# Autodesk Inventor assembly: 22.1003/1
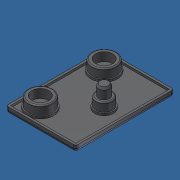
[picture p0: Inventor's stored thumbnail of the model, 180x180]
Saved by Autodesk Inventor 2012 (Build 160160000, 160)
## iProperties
Created: 2012-03
Part Number: 22.1003/1
Document SubType Name: Assembly
Designer: Administrator
Description: END CAP 45x32 Z GRAY
Vendor: S
Mass: 4.10321 g
Surface Area: 46.1556 cm^2
Volume: 3.87095 cm^3
Density: 1.06 g/cm^3
Author: Administrator
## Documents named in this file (3)
- C:\Andys Backup Data\ANDY'S INVENTOR\INVENTOR LIBRARIES\PARTS LIBRARY\END CAPS\22.1003_1 END CAP 45x32 Z Gray.iam
- C:\Andys Backup Data\ANDY'S INVENTOR\INVENTOR LIBRARIES\PARTS LIBRARY\END CAPS\SUBCOMPONENTS\22.1003_1 END CAP 45X32 GRAY.ipt
- C:\Andys Backup Data\ANDY'S INVENTOR\INVENTOR LIBRARIES\PARTS LIBRARY\END CAPS\SUBCOMPONENTS\END CAP DOWEL GRAY.ipt
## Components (2 placed, 2 different names)
1. 22.1003_1 END CAP 45X32 GRAY:1 — Mate:1, Flush:1
2. END CAP DOWEL GRAY:1 — Mate:1, Flush:1
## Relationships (2: Mate 1, Flush 1)
- Mate:1: 22.1003_1 END CAP 45X32 GRAY:1 ↔ END CAP DOWEL GRAY:1
- Flush:1: 22.1003_1 END CAP 45X32 GRAY:1 ↔ END CAP DOWEL GRAY:1
